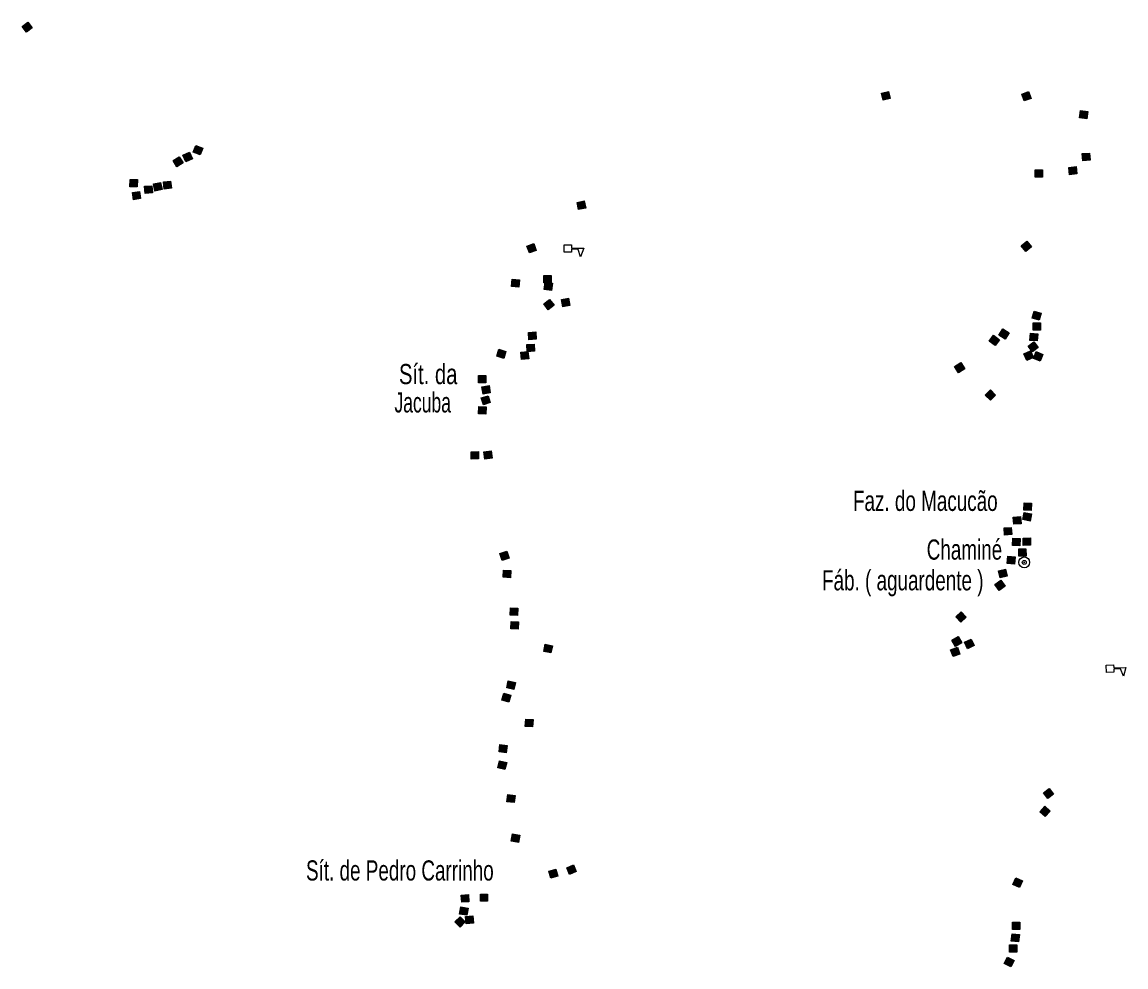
# Model space of a CAD drawing. Extents: x 679 to 705, y 7427.4 to 7455.4.
# Drawn here: x 683.589 to 687.971, y 7443.856 to 7447.606 of the extents above; entities that cross this region are included whole.
import ezdxf

# ---------------------------------------------------------------- set-up
doc = ezdxf.new("R2010")
doc.units = 0
doc.header["$LTSCALE"] = 0.032
doc.header["$PDMODE"] = 32
doc.header["$PDSIZE"] = 0.016
for name, color, linetype, lineweight in [('2', 7, 'Continuous', 25), ('4', 7, 'Continuous', 25), ('47', 7, 'Continuous', 25)]:
    doc.layers.add(name, color=color, linetype=linetype, lineweight=lineweight)
doc.layers.add('61', color=7, linetype='Continuous')

msp = doc.modelspace()

# ---------------------------------------------------------------- hatches: boundary and pattern name
at = {"layer": '2'}
for points in [[(683.6125, 7447.606), (683.63, 7447.5828), (683.6068, 7447.5654), (683.5894, 7447.5886)], [(687.0285, 7447.3308), (687.0355, 7447.3027), (687.0074, 7447.2957), (687.0003, 7447.3238)], [(687.5846, 7447.3302), (687.5947, 7447.303), (687.5676, 7447.2929), (687.5574, 7447.3201)], [(687.8201, 7447.251), (687.8162, 7447.2223), (687.7874, 7447.2262), (687.7914, 7447.255)], [(684.254, 7447.0899), (684.2663, 7447.0636), (684.2401, 7447.0513), (684.2278, 7447.0776)], [(684.2797, 7447.1164), (684.3066, 7447.1055), (684.2958, 7447.0786), (684.2689, 7447.0895)], [(684.2135, 7447.0713), (684.2289, 7447.0467), (684.2043, 7447.0314), (684.1889, 7447.056)], [(687.827, 7447.0863), (687.8289, 7447.0574), (687.7999, 7447.0555), (687.798, 7447.0844)], [(687.6395, 7447.0197), (687.6395, 7446.9907), (687.6105, 7446.9907), (687.6105, 7447.0197)], [(687.7734, 7447.0323), (687.7766, 7447.0035), (687.7478, 7447.0003), (687.7446, 7447.0291)], [(684.018, 7446.9813), (684.047, 7446.9808), (684.0465, 7446.9518), (684.0175, 7446.9523)], [(684.1393, 7446.9695), (684.1452, 7446.9411), (684.1168, 7446.9352), (684.1109, 7446.9636)], [(684.179, 7446.9749), (684.1823, 7446.9461), (684.1535, 7446.9428), (684.1502, 7446.9716)], [(684.0558, 7446.9338), (684.0599, 7446.9051), (684.0312, 7446.9009), (684.0271, 7446.9296)], [(684.105, 7446.9566), (684.1065, 7446.9276), (684.0776, 7446.9261), (684.076, 7446.955)], [(685.8206, 7446.8962), (685.8268, 7446.8679), (685.7984, 7446.8617), (685.7923, 7446.8901)], [(685.6205, 7446.7268), (685.6306, 7446.6996), (685.6034, 7446.6895), (685.5933, 7446.7167)], [(687.5785, 7446.7363), (687.5965, 7446.7136), (687.5738, 7446.6956), (687.5558, 7446.7183)], [(685.5637, 7446.5828), (685.5609, 7446.5539), (685.532, 7446.5567), (685.5348, 7446.5856)], [(685.6899, 7446.6001), (685.6899, 7446.5711), (685.6609, 7446.5711), (685.6609, 7446.6001)], [(685.6948, 7446.5695), (685.691, 7446.5408), (685.6623, 7446.5445), (685.6661, 7446.5733)], [(685.6834, 7446.5049), (685.7011, 7446.482), (685.6782, 7446.4643), (685.6605, 7446.4872)], [(685.7588, 7446.5099), (685.7643, 7446.4814), (685.7358, 7446.4759), (685.7304, 7446.5044)], [(687.6347, 7446.4508), (687.627, 7446.4229), (687.5991, 7446.4306), (687.6068, 7446.4585)], [(687.4829, 7446.3881), (687.5073, 7446.3724), (687.4915, 7446.348), (687.4672, 7446.3637)], [(687.6315, 7446.4118), (687.6315, 7446.3828), (687.6025, 7446.3828), (687.6025, 7446.4118)], [(685.6283, 7446.3761), (685.6304, 7446.3472), (685.6015, 7446.3451), (685.5994, 7446.374)], [(687.4461, 7446.3629), (687.4692, 7446.3453), (687.4516, 7446.3222), (687.4285, 7446.3398)], [(687.6215, 7446.3692), (687.619, 7446.3403), (687.5901, 7446.3427), (687.5926, 7446.3716)], [(685.51, 7446.299), (685.5018, 7446.2712), (685.4739, 7446.2793), (685.4821, 7446.3072)], [(685.6222, 7446.328), (685.6238, 7446.2991), (685.5949, 7446.2974), (685.5932, 7446.3264)], [(687.5925, 7446.3014), (687.6047, 7446.2751), (687.5785, 7446.2628), (687.5662, 7446.2891)], [(687.6061, 7446.3374), (687.6235, 7446.3142), (687.6003, 7446.2968), (687.5829, 7446.32)], [(685.5975, 7446.2984), (685.6006, 7446.2695), (685.5718, 7446.2664), (685.5686, 7446.2952)], [(687.6153, 7446.2978), (687.642, 7446.2863), (687.6306, 7446.2597), (687.6039, 7446.2711)], [(687.3158, 7446.2542), (687.3313, 7446.2297), (687.3068, 7446.2142), (687.2913, 7446.2387)], [(685.4298, 7446.2025), (685.4298, 7446.1735), (685.4008, 7446.1735), (685.4008, 7446.2025)], [(685.4432, 7446.1631), (685.448, 7446.1345), (685.4194, 7446.1297), (685.4146, 7446.1583)], [(687.4336, 7446.1458), (687.4539, 7446.1251), (687.4333, 7446.1048), (687.4129, 7446.1254)], [(685.4321, 7446.0789), (685.4306, 7446.05), (685.4016, 7446.0515), (685.4031, 7446.0804)], [(685.4392, 7446.123), (685.4481, 7446.0954), (685.4205, 7446.0865), (685.4116, 7446.1141)], [(685.4007, 7445.9013), (685.4014, 7445.8723), (685.3724, 7445.8716), (685.3717, 7445.9006)], [(685.4518, 7445.9042), (685.4555, 7445.8755), (685.4268, 7445.8717), (685.423, 7445.9004)], [(687.5963, 7445.6959), (687.5946, 7445.667), (687.5656, 7445.6687), (687.5673, 7445.6976)], [(687.5531, 7445.6434), (687.555, 7445.6144), (687.5261, 7445.6125), (687.5241, 7445.6414)], [(687.5963, 7445.6541), (687.5908, 7445.6256), (687.5623, 7445.6311), (687.5678, 7445.6595)], [(687.5163, 7445.6004), (687.5184, 7445.5715), (687.4895, 7445.5693), (687.4874, 7445.5982)], [(687.5513, 7445.5559), (687.5503, 7445.5269), (687.5213, 7445.5279), (687.5223, 7445.5569)], [(687.5919, 7445.5583), (687.5927, 7445.5293), (687.5637, 7445.5285), (687.5629, 7445.5575)], [(687.5745, 7445.5152), (687.5751, 7445.4862), (687.5461, 7445.4855), (687.5455, 7445.5145)], [(685.5138, 7445.5057), (685.5232, 7445.4783), (685.4958, 7445.4689), (685.4864, 7445.4964)], [(687.5309, 7445.4838), (687.5293, 7445.4548), (687.5003, 7445.4564), (687.5019, 7445.4854)], [(685.5294, 7445.4296), (685.5278, 7445.4006), (685.4988, 7445.4022), (685.5004, 7445.4311)], [(687.4932, 7445.4346), (687.4997, 7445.4063), (687.4714, 7445.3998), (687.4649, 7445.4281)], [(687.4746, 7445.3907), (687.4912, 7445.3669), (687.4674, 7445.3503), (687.4508, 7445.3741)], [(685.5571, 7445.2794), (685.5555, 7445.2504), (685.5265, 7445.252), (685.5281, 7445.281)], [(687.317, 7445.2649), (687.337, 7445.2439), (687.316, 7445.2239), (687.296, 7445.2449)], [(685.5604, 7445.225), (685.5585, 7445.1961), (685.5296, 7445.1979), (685.5315, 7445.2269)], [(687.3057, 7445.1669), (687.3201, 7445.1417), (687.2948, 7445.1274), (687.2805, 7445.1526)], [(685.6945, 7445.1303), (685.6885, 7445.1019), (685.6601, 7445.1079), (685.6661, 7445.1363)], [(687.3027, 7445.1243), (687.3122, 7445.0969), (687.2848, 7445.0873), (687.2753, 7445.1147)], [(687.3564, 7445.157), (687.369, 7445.1308), (687.3428, 7445.1183), (687.3303, 7445.1444)], [(685.5479, 7444.9849), (685.5416, 7444.9566), (685.5133, 7444.9629), (685.5196, 7444.9912)], [(685.5292, 7444.9347), (685.5217, 7444.9067), (685.4937, 7444.9143), (685.5012, 7444.9423)], [(685.6178, 7444.8373), (685.616, 7444.8084), (685.587, 7444.8102), (685.5888, 7444.8391)], [(685.5149, 7444.7343), (685.5113, 7444.7055), (685.4826, 7444.7091), (685.4861, 7444.7379)], [(685.5131, 7444.667), (685.5061, 7444.6389), (685.4779, 7444.6459), (685.4849, 7444.674)], [(687.6666, 7444.5644), (687.6843, 7444.5414), (687.6614, 7444.5237), (687.6436, 7444.5466)], [(685.5469, 7444.5364), (685.5431, 7444.5076), (685.5143, 7444.5114), (685.5182, 7444.5402)], [(687.6706, 7444.4739), (687.6512, 7444.4523), (687.6296, 7444.4717), (687.649, 7444.4933)], [(685.5649, 7444.3788), (685.5602, 7444.3501), (685.5315, 7444.3549), (685.5363, 7444.3835)], [(685.7084, 7444.2439), (685.7163, 7444.216), (685.6884, 7444.2081), (685.6805, 7444.236)], [(685.7778, 7444.2609), (685.7894, 7444.2343), (685.7627, 7444.2228), (685.7512, 7444.2494)], [(687.561, 7444.197), (687.5486, 7444.1707), (687.5224, 7444.1831), (687.5348, 7444.2094)], [(685.3617, 7444.1426), (685.3634, 7444.1137), (685.3344, 7444.112), (685.3327, 7444.1409)], [(685.4375, 7444.145), (685.4375, 7444.116), (685.4085, 7444.116), (685.4085, 7444.145)], [(685.3311, 7444.0941), (685.3597, 7444.0894), (685.355, 7444.0607), (685.3264, 7444.0654)], [(685.328, 7444.0548), (685.3485, 7444.0343), (685.328, 7444.0138), (685.3075, 7444.0343)], [(685.3784, 7444.0587), (685.3817, 7444.0299), (685.3529, 7444.0266), (685.3496, 7444.0554)], [(687.55, 7444.0334), (687.55, 7444.0044), (687.521, 7444.0044), (687.521, 7444.0334)], [(687.5483, 7443.9839), (687.545, 7443.9551), (687.5162, 7443.9583), (687.5194, 7443.9872)], [(687.5385, 7443.9434), (687.5385, 7443.9144), (687.5095, 7443.9144), (687.5095, 7443.9434)], [(687.5275, 7443.8814), (687.5141, 7443.8556), (687.4884, 7443.869), (687.5017, 7443.8947)]]:
    msp.add_hatch(color=256, dxfattribs=at).paths.add_polyline_path(points)

# ---------------------------------------------------------------- linework, layer by layer
for points in [[(683.6125, 7447.606), (683.63, 7447.5828), (683.6068, 7447.5654), (683.5894, 7447.5886)], [(687.0285, 7447.3308), (687.0355, 7447.3027), (687.0074, 7447.2957), (687.0003, 7447.3238)], [(687.5846, 7447.3302), (687.5947, 7447.303), (687.5676, 7447.2929), (687.5574, 7447.3201)], [(687.8201, 7447.251), (687.8162, 7447.2223), (687.7874, 7447.2262), (687.7914, 7447.255)], [(684.254, 7447.0899), (684.2663, 7447.0636), (684.2401, 7447.0513), (684.2278, 7447.0776)], [(684.2797, 7447.1164), (684.3066, 7447.1055), (684.2958, 7447.0786), (684.2689, 7447.0895)], [(684.2135, 7447.0713), (684.2289, 7447.0467), (684.2043, 7447.0314), (684.1889, 7447.056)], [(687.827, 7447.0863), (687.8289, 7447.0574), (687.7999, 7447.0555), (687.798, 7447.0844)], [(687.6395, 7447.0197), (687.6395, 7446.9907), (687.6105, 7446.9907), (687.6105, 7447.0197)], [(687.7734, 7447.0323), (687.7766, 7447.0035), (687.7478, 7447.0003), (687.7446, 7447.0291)], [(684.018, 7446.9813), (684.047, 7446.9808), (684.0465, 7446.9518), (684.0175, 7446.9523)], [(684.1393, 7446.9695), (684.1452, 7446.9411), (684.1168, 7446.9352), (684.1109, 7446.9636)], [(684.179, 7446.9749), (684.1823, 7446.9461), (684.1535, 7446.9428), (684.1502, 7446.9716)], [(684.0558, 7446.9338), (684.0599, 7446.9051), (684.0312, 7446.9009), (684.0271, 7446.9296)], [(684.105, 7446.9566), (684.1065, 7446.9276), (684.0776, 7446.9261), (684.076, 7446.955)], [(685.8206, 7446.8962), (685.8268, 7446.8679), (685.7984, 7446.8617), (685.7923, 7446.8901)], [(685.6205, 7446.7268), (685.6306, 7446.6996), (685.6034, 7446.6895), (685.5933, 7446.7167)], [(687.5785, 7446.7363), (687.5965, 7446.7136), (687.5738, 7446.6956), (687.5558, 7446.7183)], [(685.5637, 7446.5828), (685.5609, 7446.5539), (685.532, 7446.5567), (685.5348, 7446.5856)], [(685.6899, 7446.6001), (685.6899, 7446.5711), (685.6609, 7446.5711), (685.6609, 7446.6001)], [(685.6948, 7446.5695), (685.691, 7446.5408), (685.6623, 7446.5445), (685.6661, 7446.5733)], [(685.6834, 7446.5049), (685.7011, 7446.482), (685.6782, 7446.4643), (685.6605, 7446.4872)], [(685.7588, 7446.5099), (685.7643, 7446.4814), (685.7358, 7446.4759), (685.7304, 7446.5044)], [(687.6347, 7446.4508), (687.627, 7446.4229), (687.5991, 7446.4306), (687.6068, 7446.4585)], [(687.4829, 7446.3881), (687.5073, 7446.3724), (687.4915, 7446.348), (687.4672, 7446.3637)], [(687.6315, 7446.4118), (687.6315, 7446.3828), (687.6025, 7446.3828), (687.6025, 7446.4118)], [(685.6283, 7446.3761), (685.6304, 7446.3472), (685.6015, 7446.3451), (685.5994, 7446.374)], [(687.4461, 7446.3629), (687.4692, 7446.3453), (687.4516, 7446.3222), (687.4285, 7446.3398)], [(687.6215, 7446.3692), (687.619, 7446.3403), (687.5901, 7446.3427), (687.5926, 7446.3716)], [(685.51, 7446.299), (685.5018, 7446.2712), (685.4739, 7446.2793), (685.4821, 7446.3072)], [(685.6222, 7446.328), (685.6238, 7446.2991), (685.5949, 7446.2974), (685.5932, 7446.3264)], [(687.5925, 7446.3014), (687.6047, 7446.2751), (687.5785, 7446.2628), (687.5662, 7446.2891)], [(687.6061, 7446.3374), (687.6235, 7446.3142), (687.6003, 7446.2968), (687.5829, 7446.32)], [(685.5975, 7446.2984), (685.6006, 7446.2695), (685.5718, 7446.2664), (685.5686, 7446.2952)], [(687.6153, 7446.2978), (687.642, 7446.2863), (687.6306, 7446.2597), (687.6039, 7446.2711)], [(687.3158, 7446.2542), (687.3313, 7446.2297), (687.3068, 7446.2142), (687.2913, 7446.2387)], [(685.4298, 7446.2025), (685.4298, 7446.1735), (685.4008, 7446.1735), (685.4008, 7446.2025)], [(685.4432, 7446.1631), (685.448, 7446.1345), (685.4194, 7446.1297), (685.4146, 7446.1583)], [(687.4336, 7446.1458), (687.4539, 7446.1251), (687.4333, 7446.1048), (687.4129, 7446.1254)], [(685.4321, 7446.0789), (685.4306, 7446.05), (685.4016, 7446.0515), (685.4031, 7446.0804)], [(685.4392, 7446.123), (685.4481, 7446.0954), (685.4205, 7446.0865), (685.4116, 7446.1141)], [(685.4007, 7445.9013), (685.4014, 7445.8723), (685.3724, 7445.8716), (685.3717, 7445.9006)], [(685.4518, 7445.9042), (685.4555, 7445.8755), (685.4268, 7445.8717), (685.423, 7445.9004)], [(687.5963, 7445.6959), (687.5946, 7445.667), (687.5656, 7445.6687), (687.5673, 7445.6976)], [(687.5531, 7445.6434), (687.555, 7445.6144), (687.5261, 7445.6125), (687.5241, 7445.6414)], [(687.5963, 7445.6541), (687.5908, 7445.6256), (687.5623, 7445.6311), (687.5678, 7445.6595)], [(687.5163, 7445.6004), (687.5184, 7445.5715), (687.4895, 7445.5693), (687.4874, 7445.5982)], [(687.5513, 7445.5559), (687.5503, 7445.5269), (687.5213, 7445.5279), (687.5223, 7445.5569)], [(687.5919, 7445.5583), (687.5927, 7445.5293), (687.5637, 7445.5285), (687.5629, 7445.5575)], [(687.5745, 7445.5152), (687.5751, 7445.4862), (687.5461, 7445.4855), (687.5455, 7445.5145)], [(685.5138, 7445.5057), (685.5232, 7445.4783), (685.4958, 7445.4689), (685.4864, 7445.4964)], [(687.5309, 7445.4838), (687.5293, 7445.4548), (687.5003, 7445.4564), (687.5019, 7445.4854)], [(685.5294, 7445.4296), (685.5278, 7445.4006), (685.4988, 7445.4022), (685.5004, 7445.4311)], [(687.4932, 7445.4346), (687.4997, 7445.4063), (687.4714, 7445.3998), (687.4649, 7445.4281)], [(687.4746, 7445.3907), (687.4912, 7445.3669), (687.4674, 7445.3503), (687.4508, 7445.3741)], [(685.5571, 7445.2794), (685.5555, 7445.2504), (685.5265, 7445.252), (685.5281, 7445.281)], [(687.317, 7445.2649), (687.337, 7445.2439), (687.316, 7445.2239), (687.296, 7445.2449)], [(685.5604, 7445.225), (685.5585, 7445.1961), (685.5296, 7445.1979), (685.5315, 7445.2269)], [(687.3057, 7445.1669), (687.3201, 7445.1417), (687.2948, 7445.1274), (687.2805, 7445.1526)], [(685.6945, 7445.1303), (685.6885, 7445.1019), (685.6601, 7445.1079), (685.6661, 7445.1363)], [(687.3027, 7445.1243), (687.3122, 7445.0969), (687.2848, 7445.0873), (687.2753, 7445.1147)], [(687.3564, 7445.157), (687.369, 7445.1308), (687.3428, 7445.1183), (687.3303, 7445.1444)], [(685.5479, 7444.9849), (685.5416, 7444.9566), (685.5133, 7444.9629), (685.5196, 7444.9912)], [(685.5292, 7444.9347), (685.5217, 7444.9067), (685.4937, 7444.9143), (685.5012, 7444.9423)], [(685.6178, 7444.8373), (685.616, 7444.8084), (685.587, 7444.8102), (685.5888, 7444.8391)], [(685.5149, 7444.7343), (685.5113, 7444.7055), (685.4826, 7444.7091), (685.4861, 7444.7379)], [(685.5131, 7444.667), (685.5061, 7444.6389), (685.4779, 7444.6459), (685.4849, 7444.674)], [(687.6666, 7444.5644), (687.6843, 7444.5414), (687.6614, 7444.5237), (687.6436, 7444.5466)], [(685.5469, 7444.5364), (685.5431, 7444.5076), (685.5143, 7444.5114), (685.5182, 7444.5402)], [(687.6706, 7444.4739), (687.6512, 7444.4523), (687.6296, 7444.4717), (687.649, 7444.4933)], [(685.5649, 7444.3788), (685.5602, 7444.3501), (685.5315, 7444.3549), (685.5363, 7444.3835)], [(685.7084, 7444.2439), (685.7163, 7444.216), (685.6884, 7444.2081), (685.6805, 7444.236)], [(685.7778, 7444.2609), (685.7894, 7444.2343), (685.7627, 7444.2228), (685.7512, 7444.2494)], [(687.561, 7444.197), (687.5486, 7444.1707), (687.5224, 7444.1831), (687.5348, 7444.2094)], [(685.3617, 7444.1426), (685.3634, 7444.1137), (685.3344, 7444.112), (685.3327, 7444.1409)], [(685.4375, 7444.145), (685.4375, 7444.116), (685.4085, 7444.116), (685.4085, 7444.145)], [(685.3311, 7444.0941), (685.3597, 7444.0894), (685.355, 7444.0607), (685.3264, 7444.0654)], [(685.328, 7444.0548), (685.3485, 7444.0343), (685.328, 7444.0138), (685.3075, 7444.0343)], [(685.3784, 7444.0587), (685.3817, 7444.0299), (685.3529, 7444.0266), (685.3496, 7444.0554)], [(687.55, 7444.0334), (687.55, 7444.0044), (687.521, 7444.0044), (687.521, 7444.0334)], [(687.5483, 7443.9839), (687.545, 7443.9551), (687.5162, 7443.9583), (687.5194, 7443.9872)], [(687.5385, 7443.9434), (687.5385, 7443.9144), (687.5095, 7443.9144), (687.5095, 7443.9434)], [(687.5275, 7443.8814), (687.5141, 7443.8556), (687.4884, 7443.869), (687.5017, 7443.8947)]]:
    msp.add_lwpolyline(points, close=True, dxfattribs=at)
at = {"layer": '4'}
for points in [[(685.7703, 7446.7043), (685.7701, 7446.6922), (685.7411, 7446.6927), (685.7416, 7446.7217), (685.7706, 7446.7212), (685.7704, 7446.7092)], [(685.7704, 7446.7092), (685.8188, 7446.7084), (685.8066, 7446.6747), (685.7964, 7446.7039), (685.7703, 7446.7043)], [(687.9231, 7445.0374), (687.9236, 7445.0253), (687.8947, 7445.0241), (687.8934, 7445.053), (687.9224, 7445.0543), (687.9229, 7445.0423)], [(687.9229, 7445.0423), (687.9712, 7445.0444), (687.9611, 7445.0101), (687.9492, 7445.0386), (687.9231, 7445.0374)]]:
    msp.add_lwpolyline(points, dxfattribs=at)
at = {"layer": '47'}
msp.add_circle((687.5676, 7445.4613), 0.0215, dxfattribs=at)
msp.add_point((687.5676, 7445.4611), dxfattribs=at)

# ---------------------------------------------------------------- texts
at = {"layer": '61'}
for s, width, p in [('Sít. da ', 0.75, (685.0856, 7446.1688)), ('Jacuba', 0.65, (685.0676, 7446.0563)), ('Faz. do Macucão', 0.7, (686.8877, 7445.6656)), ('Chaminé', 0.7, (687.1804, 7445.4722)), ('Fáb. ( aguardente )', 0.7, (686.7649, 7445.3503)), ('Sít. de Pedro Carrinho', 0.7, (684.7165, 7444.1985))]:
    msp.add_text(s, height=0.08, dxfattribs=dict(at, width=width)).set_placement(p)

doc.saveas('drawing.dxf')
